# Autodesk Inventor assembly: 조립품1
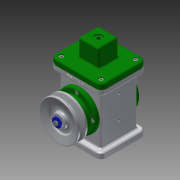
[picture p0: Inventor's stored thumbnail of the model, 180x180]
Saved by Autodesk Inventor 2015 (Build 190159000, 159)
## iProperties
Created: 2017-08
Part Number: 조립품1
Document SubType Name: Assembly
Designer: Administrator
Author: Administrator
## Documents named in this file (18)
- C:\Users\Administrator\Desktop\470807V1003\조립품1.iam
- C:\Users\Administrator\Desktop\470807V1003\본체.ipt
- C:\Users\Administrator\Desktop\470807V1003ㅁㅁ\E-링.ipt
- C:\Users\Administrator\Desktop\470807V1003ㅁㅁ\V-벨트풀리.ipt
- C:\Users\Administrator\Desktop\470807V1003ㅁㅁ\덮개.ipt
- C:\Users\Administrator\Desktop\470807V1003ㅁㅁ\뒤커버.ipt
- C:\Users\Administrator\Desktop\470807V1003ㅁㅁ\링크.ipt
- C:\Users\Administrator\Desktop\470807V1003ㅁㅁ\베어링 17 x 40 x 12.ipt
- C:\Users\Administrator\Desktop\470807V1003ㅁㅁ\볼트 M4 x 8.ipt
- C:\Users\Administrator\Desktop\470807V1003ㅁㅁ\볼트 M4 x 10.ipt
- C:\Users\Administrator\Desktop\470807V1003ㅁㅁ\슬라이더.ipt
- C:\Users\Administrator\Desktop\470807V1003ㅁㅁ\앞커버.ipt
- C:\Users\Administrator\Desktop\470807V1003ㅁㅁ\오일 실 17 30 8.ipt
- C:\Users\Administrator\Desktop\470807V1003ㅁㅁ\와셔 4x16.ipt
- C:\Users\Administrator\Desktop\470807V1003ㅁㅁ\클레비스 핀 6 x 22.ipt
- 클레비스 핀 6 x 22.ipt
- C:\Users\Administrator\Desktop\470807V1003ㅁㅁ\키 4 x 4 x 12.ipt
- C:\Users\Administrator\Desktop\470807V1003ㅁㅁ\편심축.ipt
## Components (2 placed, 2 different names)
1. E-링:1
2. V-벨트풀리:1
